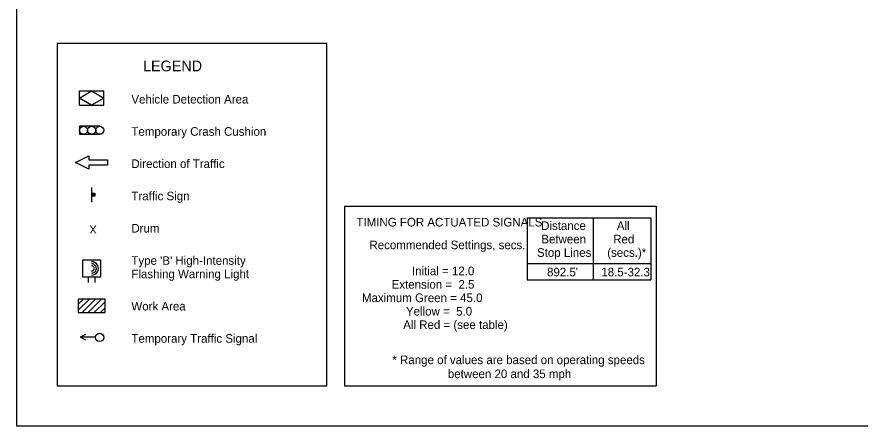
# Model space of a CAD drawing. Extents: x -2134934 to -2119606, y -2139046 to -2137036.
# Drawn here: x -2134934 to -2133366, y -2139046 to -2138285 of the extents above; entities that cross this region are included whole.
import ezdxf

# ---------------------------------------------------------------- set-up
doc = ezdxf.new("R2010")
doc.units = 0
for name, color, linetype in [('Default', 7, 'Continuous'), ('Level 2', 7, 'Continuous'), ('Level 3', 7, 'Continuous'), ('Level 4', 7, 'Continuous')]:
    doc.layers.add(name, color=color, linetype=linetype)

msp = doc.modelspace()

# ---------------------------------------------------------------- linework, layer by layer
at = {"layer": 'Default'}
msp.add_lwpolyline([(-2134934.4, -2137035.9), (-2131799.4, -2137035.9), (-2131799.4, -2139045.9), (-2134934.4, -2139045.9)], close=True, dxfattribs=at)
at = {"layer": 'Level 2'}
for p, q in [((-2134817.8, -2138449.1), (-2134817.8, -2138422.1)), ((-2134817.8, -2138422.1), (-2134772.8, -2138422.1)), ((-2134772.8, -2138449.1), (-2134772.8, -2138422.1)), ((-2134817.8, -2138449.1), (-2134772.8, -2138449.1)), ((-2134817.8, -2138488.1), (-2134817.8, -2138503.1)), ((-2134780.3, -2138488.1), (-2134817.8, -2138488.1)), ((-2134817.8, -2138503.1), (-2134780.3, -2138503.1)), ((-2134795.3, -2138601.9), (-2134795.3, -2138629.4)), ((-2134794.9, -2138618.4), (-2134794.9, -2138612.8)), ((-2134794.6, -2138612.8), (-2134794.6, -2138618.4)), ((-2134794.3, -2138618.4), (-2134794.3, -2138612.8)), ((-2134794.1, -2138612.8), (-2134794.1, -2138618.4)), ((-2134793.9, -2138618.4), (-2134793.9, -2138612.8)), ((-2134793.6, -2138612.8), (-2134793.6, -2138618.4)), ((-2134793.3, -2138618.4), (-2134793.3, -2138612.8)), ((-2134793, -2138612.8), (-2134793, -2138618.4)), ((-2134792.8, -2138618.4), (-2134792.8, -2138612.8)), ((-2134792.5, -2138612.8), (-2134792.5, -2138618.4)), ((-2134792.1, -2138618.4), (-2134792.1, -2138612.8)), ((-2134791.7, -2138612.8), (-2134791.7, -2138618.4)), ((-2134791.5, -2138618.4), (-2134791.5, -2138612.8)), ((-2134791.1, -2138612.8), (-2134791, -2138618.4)), ((-2134790.8, -2138618.4), (-2134790.8, -2138612.8)), ((-2134790.5, -2138612.8), (-2134790.5, -2138618.4)), ((-2134790.3, -2138618.4), (-2134790.3, -2138612.8)), ((-2134790, -2138612.8), (-2134790, -2138618.4)), ((-2134325, -2138636.9), (-2134325, -2138970.9)), ((-2134325, -2138636.9), (-2133745, -2138636.9)), ((-2133745, -2138636.9), (-2133745, -2138970.9)), ((-2134801.6, -2138768.8), (-2134801.6, -2138778.8)), ((-2134789.1, -2138768.8), (-2134789.1, -2138778.8)), ((-2134820.3, -2138830.5), (-2134799.3, -2138809.5)), ((-2134820.3, -2138819.2), (-2134810.6, -2138809.5)), ((-2134813, -2138834.5), (-2134788, -2138809.5)), ((-2134801.7, -2138834.5), (-2134776.7, -2138809.5)), ((-2134790.4, -2138834.5), (-2134770.3, -2138814.5)), ((-2134779, -2138834.5), (-2134770.3, -2138825.8)), ((-2134788.2, -2138880.6), (-2134816.1, -2138880.6)), ((-2134325, -2138970.9), (-2133745, -2138970.9))]:
    msp.add_line(p, q, dxfattribs=at)
for points in [[(-2134859.4, -2138970.9), (-2134357.9, -2138970.9), (-2134357.9, -2138334.3), (-2134859.4, -2138334.3)], [(-2134765.6, -2138550.6), (-2134765.6, -2138560.6), (-2134800.6, -2138560.6), (-2134800.6, -2138568.1), (-2134825.6, -2138555.6), (-2134800.6, -2138543.1), (-2134800.6, -2138550.6)], [(-2134795.2, -2138618.4), (-2134795.2, -2138612.7), (-2134789.6, -2138612.7), (-2134789.6, -2138618.4)], [(-2134811.6, -2138768.8), (-2134811.6, -2138736.3), (-2134779.1, -2138736.3), (-2134779.1, -2138768.8)], [(-2134820.3, -2138834.5), (-2134770.3, -2138834.5), (-2134770.3, -2138809.5), (-2134820.3, -2138809.5)]]:
    msp.add_lwpolyline(points, close=True, dxfattribs=at)
msp.add_lwpolyline([(-2134806.5, -2138875.7), (-2134816.5, -2138880.7), (-2134806.5, -2138885.7)], dxfattribs=at)
for centre, radius in [((-2134810.3, -2138495.6), 7.5), ((-2134810.3, -2138495.6), 7.5), ((-2134795.3, -2138495.6), 7.5), ((-2134795.3, -2138495.6), 7.5), ((-2134780.3, -2138495.6), 7.5), ((-2134780.3, -2138495.6), 7.5), ((-2134780.4, -2138880.9), 7.74)]:
    msp.add_circle(centre, radius, dxfattribs=at)
for radius in [12.5, 12.5, 8.75, 5]:
    msp.add_arc((-2134795.3, -2138752.5), radius, 269.4041, 90.5445, dxfattribs=at)
at = {"layer": 'Level 3'}
for p, q in [((-2133985, -2138658.5), (-2133985, -2138774)), ((-2133985, -2138658.5), (-2133755, -2138658.5)), ((-2133862.6, -2138658.5), (-2133862.6, -2138774)), ((-2133755, -2138658.5), (-2133755, -2138774)), ((-2133985, -2138743.5), (-2133755, -2138743.5)), ((-2133985, -2138774), (-2133755, -2138774))]:
    msp.add_line(p, q, dxfattribs=at)
at = {"layer": 'Level 4'}
msp.add_lwpolyline([(-2134817.8, -2138435.6), (-2134795.3, -2138422.1), (-2134772.8, -2138435.6), (-2134795.3, -2138449.1)], close=True, dxfattribs=at)

# ---------------------------------------------------------------- texts
at = {"layer": 'Level 2'}
msp.add_text('X', height=15, rotation=180, dxfattribs=at).set_placement((-2134785.9, -2138672.2))
at = {"layer": 'Level 3'}
for s, height, p in [('LEGEND', 20, (-2134699.8, -2138385.9)), ('Vehicle Detection Area', 16, (-2134721.4, -2138445.8)), ('Temporary Crash Cushion', 16, (-2134721.4, -2138505.8)), ('Direction of Traffic', 16, (-2134721.4, -2138565.8)), ('Traffic Sign', 16, (-2134721.4, -2138625.8)), ('Drum', 16, (-2134721.4, -2138685.8)), ('TIMING FOR ACTUATED SIGNALS', 16, (-2134302.7, -2138674.5)), ('Distance', 16, (-2133959.1, -2138681)), ('All', 16, (-2133818.3, -2138681)), ('Red', 16, (-2133825, -2138706)), ('Recommended Settings, secs.', 16, (-2134278.5, -2138716.8)), ('Between', 16, (-2133958.8, -2138706)), ('Stop Lines', 16, (-2133966.8, -2138731)), (' (secs.)*', 16, (-2133842.1, -2138731)), ("Type 'B' High-Intensity", 16, (-2134721.4, -2138745.8)), ('Initial = 12.0', 16, (-2134199.4, -2138765.2)), ("892.5'", 16, (-2133948.1, -2138767.3)), ('18.5-32.3', 16, (-2133847.1, -2138767.3)), ('Flashing Warning Light', 16, (-2134721.4, -2138770.8)), ('Extension =  2.5', 16, (-2134237.2, -2138790.2)), ('Maximum Green = 45.0', 16, (-2134292.4, -2138815.2)), ('Work Area', 16, (-2134721.4, -2138830.8)), ('Yellow =  5.0', 16, (-2134210.6, -2138840.2)), ('All Red = (see table)', 16, (-2134215.7, -2138865.2)), ('Temporary Traffic Signal', 16, (-2134721.4, -2138890.8)), ('* Range of values are based on operating speeds', 16, (-2134235.9, -2138930.6)), ('between 20 and 35 mph', 16, (-2134132.7, -2138956.6))]:
    msp.add_text(s, height=height, dxfattribs=at).set_placement(p)

doc.saveas('drawing.dxf')
